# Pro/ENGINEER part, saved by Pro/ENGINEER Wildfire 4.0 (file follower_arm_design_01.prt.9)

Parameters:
  METRIC = "NO"

Other parameters: PITCH, DRILL_DIAMETER, THREAD_DIAMETER, THREADS_PER_INCH, THREAD_DEPTH, THREAD_LENGTH, DRILL_POINT_ANGLE, DRILL_DEPTH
